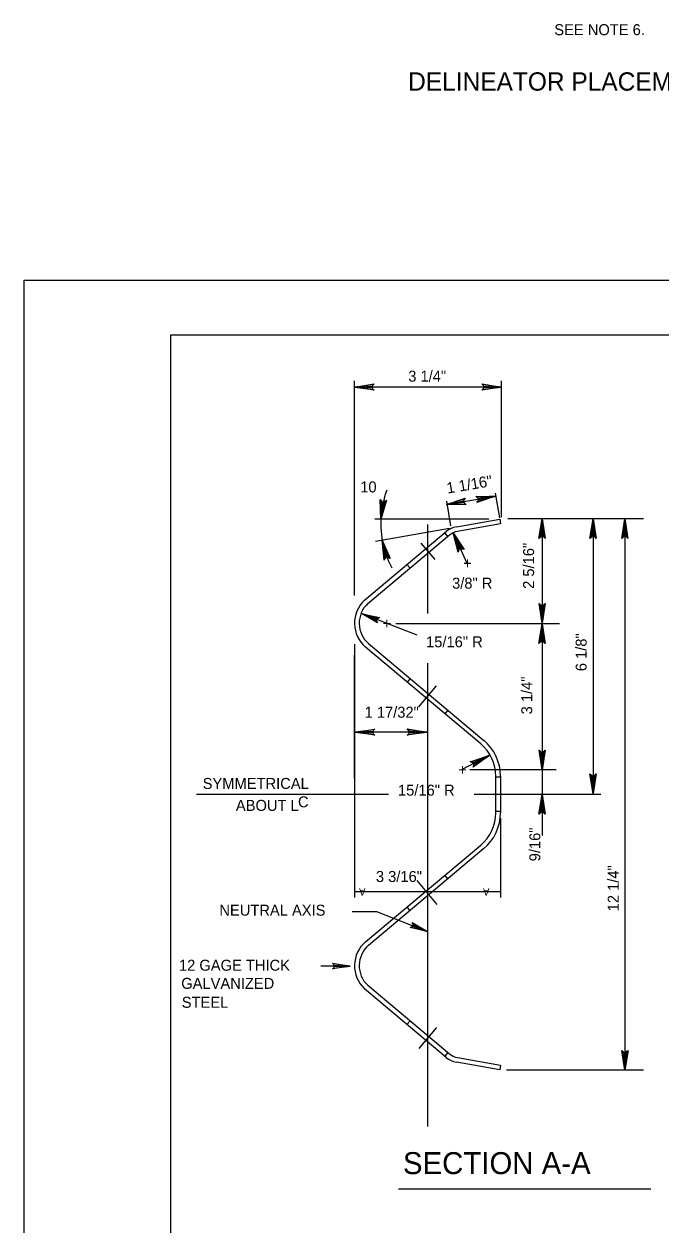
# Model space of a CAD drawing. Extents: x 637628 to 640188, y 298266 to 300751.
# Drawn here: x 638278.5 to 638452.5, y 299195.5 to 299523.5 of the extents above; entities that cross this region are included whole.
import ezdxf

# ---------------------------------------------------------------- set-up
doc = ezdxf.new("R2010")
doc.units = 0
for name, color, linetype in [('1', 7, 'Continuous'), ('2', 7, 'Continuous'), ('3', 7, 'Continuous'), ('PLT-BNDY', 7, 'Continuous')]:
    doc.layers.add(name, color=color, linetype=linetype)

msp = doc.modelspace()

# ---------------------------------------------------------------- linework, layer by layer
at = {"layer": '1'}
for points in [[(639104.52, 298874.58), (639104.52, 299438.58), (638318.52, 299438.58), (638318.52, 298874.58), (639104.52, 298874.58), (639104.52, 298900.93), (638904.52, 298900.93), (638904.52, 298965.61), (639104.52, 298965.61), (639104.52, 298994.58), (638904.52, 298994.58), (638904.52, 298874.58), (638983.33, 298874.58), (638983.33, 298900.93), (638983.33, 298874.58), (639060.33, 298874.58), (639060.33, 298900.93), (639060.33, 298888.62), (639104.52, 298888.62)], [(638362.98, 299266.84), (638363.16, 299266.51), (638367.6, 299266.26), (638362.98, 299266.84), (638362.75, 299267.04), (638367.6, 299266.26), (638363.16, 299266.04), (638363, 299265.71), (638367.6, 299266.26), (638362.75, 299265.49), (638363, 299265.71)]]:
    msp.add_lwpolyline(points, dxfattribs=at)
at = {"layer": '2'}
for p, q in [((638368.8, 299367.43), (638368.8, 299426.07)), ((638408.93, 299388.83), (638408.93, 299426.07)), ((638395.39, 299424.39), (638368.8, 299424.39)), ((638408.93, 299424.39), (638395.39, 299424.39)), ((638393.88, 299392.29), (638407.33, 299394.55)), ((638393.89, 299393.19), (638395.02, 299386.46)), ((638407.23, 299395.44), (638408.37, 299388.69)), ((638405.45, 299388.31), (638374.35, 299388.31)), ((638388.7, 299386.88), (638388.7, 299362.56)), ((638396.66, 299386.21), (638408.43, 299388.3)), ((638408.64, 299387.05), (638396.91, 299384.96)), ((638408.43, 299388.3), (638408.64, 299387.05)), ((638447.7, 299388.44), (638410.67, 299388.44)), ((638420.02, 299388.44), (638420.02, 299359.82)), ((638433.94, 299388.44), (638433.94, 299313.37)), ((638442.61, 299388.44), (638442.61, 299237.86)), ((638371.52, 299366.18), (638393.84, 299384.92)), ((638394.75, 299383.97), (638372.41, 299365.23)), ((638374.54, 299382.29), (638394.72, 299385.87)), ((638394.31, 299383.58), (638393.44, 299384.6)), ((638395.71, 299384.58), (638399.42, 299376.29)), ((638390.77, 299377.29), (638386.99, 299381.79)), ((638383.97, 299374.9), (638383.1, 299375.92)), ((638385.89, 299356.6), (638370.86, 299362.45)), ((638380.09, 299359.83), (638424.74, 299359.81)), ((638420.02, 299359.82), (638420.02, 299319.86)), ((638368.8, 299354.15), (638368.8, 299285.01)), ((638403.25, 299326.91), (638371.78, 299353.35)), ((638372.62, 299354.32), (638404.08, 299327.89)), ((638368.8, 299317.59), (638368.8, 299351.2)), ((638388.7, 299348.99), (638388.7, 299222.46)), ((638383.96, 299344.81), (638383.13, 299343.83)), ((638391.06, 299342.77), (638386.28, 299337.08)), ((638394.3, 299336.14), (638393.47, 299335.15)), ((638388.5, 299330.14), (638368.95, 299330.14)), ((638405.63, 299323.83), (638398.04, 299319.89)), ((638423.9, 299319.88), (638400.24, 299319.88)), ((638407.37, 299313.13), (638407.37, 299318.12)), ((638408.64, 299317.82), (638407.37, 299317.82)), ((638408.64, 299318.12), (638408.64, 299313.13)), ((638420.02, 299319.88), (638420.02, 299301.92)), ((638378.08, 299313.13), (638325.6, 299313.13)), ((638436.05, 299313.13), (638401.46, 299313.13)), ((638407.37, 299308.11), (638407.37, 299313.13)), ((638408.64, 299313.13), (638408.64, 299308.11)), ((638408.64, 299308.44), (638407.37, 299308.44)), ((638408.64, 299306.61), (638408.64, 299285.01)), ((638371.78, 299272.89), (638403.25, 299299.31)), ((638404.08, 299298.35), (638372.62, 299271.91)), ((638394.29, 299290.08), (638393.47, 299291.05)), ((638391.36, 299283.06), (638385.87, 299289.61)), ((638397.03, 299286.51), (638368.8, 299286.51)), ((638408.64, 299286.51), (638397.03, 299286.51)), ((638383.99, 299281.35), (638383.12, 299282.39)), ((638367.6, 299266.26), (638359.61, 299266.26)), ((638393.84, 299241.31), (638371.52, 299260.05)), ((638372.41, 299261.01), (638394.74, 299242.26)), ((638383.95, 299251.33), (638383.11, 299250.33)), ((638391.18, 299249.44), (638386.37, 299243.71)), ((638394.3, 299242.66), (638393.45, 299241.65)), ((638408.43, 299237.93), (638396.61, 299240.03)), ((638396.91, 299241.28), (638408.64, 299239.19)), ((638408.64, 299239.19), (638408.43, 299237.93)), ((638447.7, 299237.86), (638410.3, 299237.86))]:
    msp.add_line(p, q, dxfattribs=at)
for points in [[(638373.91, 299423.75), (638373.71, 299424.12), (638368.8, 299424.39), (638373.91, 299423.75), (638374.17, 299423.53), (638368.8, 299424.39), (638373.71, 299424.63), (638373.89, 299425), (638368.8, 299424.39), (638374.17, 299425.24), (638373.89, 299425)], [(638403.82, 299425.03), (638404.01, 299424.66), (638408.93, 299424.39), (638403.82, 299425.03), (638403.56, 299425.26), (638408.93, 299424.39), (638404.01, 299424.15), (638403.83, 299423.78), (638408.93, 299424.39), (638403.56, 299423.54), (638403.83, 299423.78)], [(638377.24, 299393.24), (638376.85, 299393.09), (638376, 299388.24), (638377.24, 299393.24), (638377.49, 299393.47), (638376, 299388.24), (638376.34, 299393.15), (638376, 299393.37), (638376, 299388.24), (638375.79, 299393.68), (638376, 299393.37)], [(638399.02, 299392.51), (638398.77, 299392.84), (638393.88, 299392.29), (638399.02, 299392.51), (638399.32, 299392.33), (638393.88, 299392.29), (638398.68, 299393.35), (638398.8, 299393.74), (638393.88, 299392.29), (638399.03, 299394.02), (638398.8, 299393.74)], [(638402.19, 299394.34), (638402.44, 299394), (638407.33, 299394.55), (638402.19, 299394.34), (638401.89, 299394.51), (638407.33, 299394.55), (638402.53, 299393.5), (638402.41, 299393.11), (638407.33, 299394.55), (638402.18, 299392.82), (638402.41, 299393.11)], [(638419.38, 299383.34), (638419.75, 299383.53), (638420.02, 299388.44), (638419.38, 299383.34), (638419.16, 299383.07), (638420.02, 299388.44), (638420.27, 299383.53), (638420.63, 299383.35), (638420.02, 299388.44), (638420.88, 299383.07), (638420.63, 299383.35)], [(638433.3, 299383.34), (638433.67, 299383.53), (638433.94, 299388.44), (638433.3, 299383.34), (638433.07, 299383.07), (638433.94, 299388.44), (638434.18, 299383.53), (638434.55, 299383.35), (638433.94, 299388.44), (638434.79, 299383.07), (638434.55, 299383.35)], [(638441.97, 299383.34), (638442.34, 299383.53), (638442.61, 299388.44), (638441.97, 299383.34), (638441.75, 299383.07), (638442.61, 299388.44), (638442.86, 299383.53), (638443.22, 299383.35), (638442.61, 299388.44), (638443.47, 299383.07), (638443.22, 299383.35)], [(638397.22, 299379.65), (638397.48, 299379.98), (638395.71, 299384.58), (638397.22, 299379.65), (638397.12, 299379.32), (638395.71, 299384.58), (638397.94, 299380.19), (638398.35, 299380.18), (638395.71, 299384.58), (638398.69, 299380.02), (638398.35, 299380.18)], [(638377.02, 299377.46), (638377.33, 299377.74), (638376.37, 299382.57), (638377.02, 299377.46), (638376.87, 299377.15), (638376.37, 299382.57), (638377.83, 299377.87), (638378.23, 299377.79), (638376.37, 299382.57), (638378.53, 299377.58), (638378.23, 299377.79)], [(638420.67, 299365), (638420.29, 299364.81), (638420.02, 299359.89), (638420.67, 299365), (638420.89, 299365.26), (638420.02, 299359.89), (638419.78, 299364.8), (638419.42, 299364.98), (638420.02, 299359.89), (638419.17, 299365.26), (638419.42, 299364.98)], [(638374.88, 299360.27), (638374.84, 299360.64), (638370.86, 299362.45), (638374.88, 299360.27), (638375.03, 299360), (638370.86, 299362.45), (638375.01, 299361.06), (638375.27, 299361.31), (638370.86, 299362.45), (638375.58, 299361.42), (638375.27, 299361.31)], [(638419.38, 299354.62), (638419.75, 299354.81), (638420.02, 299359.73), (638419.38, 299354.62), (638419.16, 299354.35), (638420.02, 299359.73), (638420.27, 299354.81), (638420.63, 299354.63), (638420.02, 299359.73), (638420.88, 299354.35), (638420.63, 299354.63)], [(638374.06, 299329.5), (638373.87, 299329.87), (638368.95, 299330.14), (638374.06, 299329.5), (638374.32, 299329.28), (638368.95, 299330.14), (638373.87, 299330.38), (638374.04, 299330.75), (638368.95, 299330.14), (638374.32, 299330.99), (638374.04, 299330.75)], [(638383.39, 299330.78), (638383.58, 299330.41), (638388.5, 299330.14), (638383.39, 299330.78), (638383.13, 299331.01), (638388.5, 299330.14), (638383.59, 299329.9), (638383.41, 299329.53), (638388.5, 299330.14), (638383.13, 299329.29), (638383.41, 299329.53)], [(638400.73, 299322), (638401.07, 299321.75), (638405.56, 299323.78), (638400.73, 299322), (638400.39, 299322.07), (638405.56, 299323.78), (638401.31, 299321.3), (638401.32, 299320.89), (638405.56, 299323.78), (638401.18, 299320.55), (638401.32, 299320.89)], [(638420.67, 299324.97), (638420.29, 299324.78), (638420.02, 299319.86), (638420.67, 299324.97), (638420.89, 299325.23), (638420.02, 299319.86), (638419.78, 299324.78), (638419.42, 299324.96), (638420.02, 299319.86), (638419.17, 299325.23), (638419.42, 299324.96)], [(638434.58, 299318.48), (638434.21, 299318.29), (638433.94, 299313.37), (638434.58, 299318.48), (638434.8, 299318.74), (638433.94, 299313.37), (638433.7, 299318.28), (638433.33, 299318.46), (638433.94, 299313.37), (638433.09, 299318.74), (638433.33, 299318.46)], [(638419.38, 299308.01), (638419.75, 299308.21), (638420.02, 299313.12), (638419.38, 299308.01), (638419.16, 299307.75), (638420.02, 299313.12), (638420.27, 299308.21), (638420.63, 299308.03), (638420.02, 299313.12), (638420.88, 299307.75), (638420.63, 299308.03)], [(638368.14, 299281.19), (638374.78, 299281.19)], [(638374.78, 299281.19), (638388.68, 299275.71)], [(638384.67, 299277.9), (638384.71, 299277.54), (638388.68, 299275.71), (638384.67, 299277.9), (638384.53, 299278.18), (638388.68, 299275.71), (638384.54, 299277.11), (638384.27, 299276.87), (638388.68, 299275.71), (638383.97, 299276.75), (638384.27, 299276.87)], [(638443.25, 299242.97), (638442.88, 299242.78), (638442.61, 299237.86), (638443.25, 299242.97), (638443.48, 299243.23), (638442.61, 299237.86), (638442.37, 299242.78), (638442, 299242.96), (638442.61, 299237.86), (638441.76, 299243.23), (638442, 299242.96)]]:
    msp.add_lwpolyline(points, dxfattribs=at)
for centre, radius, start, end in [((638397.63, 299380.42), 5.88, 100.0299, 130), ((638397.7, 299380.44), 4.6, 100.0505, 130.0141), ((638377.44, 299359.88), 8.65, 133.3708, 229.0394), ((638377.44, 299359.88), 7.37, 133.3708, 229.0394), ((638395.87, 299318.12), 12.78, 0, 49.9873), ((638395.87, 299318.12), 11.49, 0, 49.9873), ((638395.87, 299308.11), 11.49, 310.0127, 0), ((638395.87, 299308.11), 12.78, 310.0127, 0), ((638377.44, 299266.35), 8.65, 130.9606, 226.6292), ((638377.44, 299266.35), 7.37, 130.9606, 226.6292), ((638397.7, 299245.8), 4.6, 230.0087, 259.9673), ((638397.63, 299245.81), 5.88, 230, 259.9701)]:
    msp.add_arc(centre, radius, start, end, dxfattribs=at)
for start_param, end_param in [(5.799468, 6.321519), (6.276567, 6.553488)]:
    msp.add_ellipse((638408.16, 299388.27), major_axis=(-31.76, -5.89), ratio=0.890014, start_param=start_param, end_param=end_param, dxfattribs=at)
at = {"layer": '3'}
msp.add_line((638380.79, 299205.44), (638449.74, 299205.44), dxfattribs=at)
at = {"layer": 'PLT-BNDY'}
msp.add_lwpolyline([(638278.52, 299453.58), (639119.52, 299453.58), (639119.52, 298859.58), (638278.52, 298859.58)], close=True, dxfattribs=at)

# ---------------------------------------------------------------- texts
at = {"layer": '1'}
msp.add_text('3/8" R ', height=3, dxfattribs=at).set_placement((638395.43, 299369.32))
at = {"layer": '2'}
for s, height, p in [('SEE NOTE 6.', 3, (638423.35, 299520.5)), ('DELINEATOR PLACEMENT', 5, (638383.43, 299505.35))]:
    msp.add_text(s, height=height, dxfattribs=at).set_placement(p)
for p in [(638371.8, 299287.51), (638405.64, 299287.51)]:
    msp.add_text('A', height=2, rotation=180, dxfattribs=at).set_placement(p)
at = {"layer": '3'}
for s, height, p in [('3 1/4"', 3, (638383.46, 299425.86)), ('10', 3, (638370.34, 299395.62)), ('+', 3, (638398.46, 299374.79)), ('+', 3, (638376.47, 299358.38)), ('15/16" R ', 3, (638388.33, 299353.31)), ('1 17/32"', 3, (638371.54, 299334.08)), ('+', 3, (638397.08, 299318.39)), ('SYMMETRICAL', 3, (638327.32, 299314.63)), ('15/16" R ', 3, (638380.66, 299312.8)), ('ABOUT L', 3, (638336.39, 299308.63)), ('C', 3, (638353.35, 299309.6)), ('3 3/16"', 3, (638374.63, 299289.22)), ('NEUTRAL AXIS', 3, (638331.87, 299280.01)), ('12 GAGE THICK', 3, (638320.84, 299264.98)), ('GALVANIZED', 3, (638321.46, 299260.03)), ('STEEL', 3, (638321.6, 299254.86)), ('SECTION A-A', 6, (638382.01, 299209.43))]:
    msp.add_text(s, height=height, dxfattribs=at).set_placement(p)
for s, rotation, p in [('1 1/16"', 9.5395, (638394.19, 299395.28)), ('2 5/16"', 90, (638417.83, 299369.27)), ('6 1/8"', 90, (638432.18, 299346.79)), ('3 1/4"', 90, (638417.33, 299334.99)), ('9/16"', 90, (638419.53, 299294.86)), ('12 1/4"', 90, (638440.94, 299281.2))]:
    msp.add_text(s, height=3, rotation=rotation, dxfattribs=at).set_placement(p)

doc.saveas('drawing.dxf')
